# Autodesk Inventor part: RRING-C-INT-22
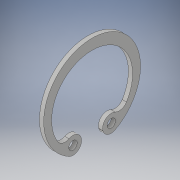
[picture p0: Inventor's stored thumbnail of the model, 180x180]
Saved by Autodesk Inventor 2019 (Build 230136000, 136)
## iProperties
Created: 2022-11
Part Number: RRING-C-INT-22
Material: Generic
Catalog Web Link: www.cadenas.de
Description: RRING_C_INT-Retaining Rings - C  (Internal)
Vendor: MISUMI
Document SubType Name: Modeling
Designer: psAdmin
Manufacturer: MISUMI
Mass: 0.128626 g
Surface Area: 3.94561 cm^2
Volume: 0.128626 cm^3
Density: 1 g/cm^3
Appearance: PSOLRGB-175-175-175
Category: PARTsolutions
Company: MISUMI
Title: RRING-C-INT-22
Author: Cadenas PARTsolutions
Comments: Retaining Rings - C  (Internal)
PSOL_IDENT_0: {$CADENAS_DATA/23d-libs/misumi/metric/accessories/rring_c_int.prj},177 {VTYP=3D},{NB=RRING-C-INT-22}
PSOL_IDENT_1: ,{LINA=RRING-C-INT-22},{NN=RRING_C_INT},{DATE=30.06.2021 13:30:10},{GEOMDATE=05.03.2015 00:00:00},{V
PSOL_IDENT_2: ERSION=},{LINEID=120},{WBVAR=MAT},{WBNUMERIC=}  {NB=RRING-C-INT-22},{LINA=RRING-C-INT-22},{KT=DUMMY}
PSOL_IDENT_3: ,{PN=RRING-C-INT-22},{TYPE=RRING-C-INT},{MAT=},{HARD=36~44HRC},{NO=22},{DD3=23.5},{DD3TOL=+0.2/-0.2}
PSOL_IDENT_4: ,{TT=1.00},{TTTOL=+0.05/-0.05},{BB=2.5},{AA=4.1},{DD0=2.0},{DD4=13},{DD1=22},{DD2=23.0},{DD2TOL=+0.2
PSOL_IDENT_5: 1/0},{MM=1.15},{MMTOL=+0.14/0},{NN=1.5},{A2=9.10}
NB: RRING-C-INT-22
NN: 1.5
NT: Retaining Rings - C  (Internal)
NBSYN: $PN.
LINA: RRING-C-INT-22
CATALOG: Misumi
PN: RRING-C-INT-22
MAT: Spring Steel
HARD: 36~44HRC
NO: 22
DD3: 23.5
DD3TOL: +0.2/-0.2
TT: 1
TTTOL: +0.05/-0.05
BB: 2.5
AA: 4.1
DD0: 2
DD4: 13
DD1: 22
DD2: 23
DD2TOL: +0.21/0
MM: 1.15
MMTOL: +0.14/0
SUPPLIER: MISUMI
ARTICLENO: RRING-C-INT-22
BOMINFO: RRING-C-INT-22
CREATOR: CADENAS GmbH
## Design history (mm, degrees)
sketch "Sketch_3"
  geometry: L1 (-8.916, 2.599)-(-8.856, 2.582); L2 (-8.856, -2.582)-(-8.916, -2.599); C1 r 1 at (-8.283, -4.55); C2 r 1 at (-8.283, 4.55); A1 r 11.5 centre (0, 0) between (-10.115, -5.471) and (-10.115, 5.471); A2 r 2 centre (-8.356, 4.519) between (-10.115, 5.471) and (-8.916, 2.599); A3 r 2.05 centre (-8.283, 4.55) between (-8.856, 2.582) and (-6.46, 5.488); A4 r 2.05 centre (-4.637, 6.426) between (-5.722, 8.164) and (-6.46, 5.488); A5 r 9.625 centre (-0.625, 0) between (-5.722, -8.164) and (-5.722, 8.164); A6 r 2.05 centre (-4.637, -6.426) between (-6.46, -5.488) and (-5.722, -8.164); A7 r 2.05 centre (-8.283, -4.55) between (-6.46, -5.488) and (-8.856, -2.582); A8 r 2 centre (-8.356, -4.519) between (-8.916, -2.599) and (-10.115, -5.471); 2 further points
  constraints: 16 point on circle, 10 centre point, 4 end point
extrude "Extrusion1" join sketch "Sketch_3" stored distance "d0" = 1; taper "d1" = 0 deg
node "rr_XY"
node "rr_YZ"
node "rr_ZX"
node "rr_X"
node "rr_Y"
node "rr_Z"
node "rr_Center"
body "Solid1"
other parameters: "d2" = 0
